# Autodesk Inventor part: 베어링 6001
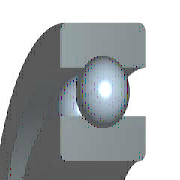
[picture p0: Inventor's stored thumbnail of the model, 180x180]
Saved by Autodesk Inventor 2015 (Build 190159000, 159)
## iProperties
IsCustomPart: 0
Created: 2015-10
Part Number: 베어링 6001
Material: Steel, Mild
Description: 깊은 그루브 볼 베어링
Document SubType Name: Modeling
Standard: KS B 2023
Designer: mdu
Standards Organization: KS
Language: ko-KR
Size Designation: 6001 - 12 x 28 x 8
Categories: <MemberInstance><Categories><Category DisplayName="샤프트 부품" InternalName="7f7aeb1f-a693-4053-b835-cee3144e0d98" Mnemonic="SHFT"><Category DisplayName="베어링" Inter
Density: 1 g/cm^3
Appearance: Steel
Author: mdu
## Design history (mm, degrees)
revolve "본체" stored, may be unused: angle "d6" = 90 deg
revolve "볼" stored, may be unused: angle "d7" = 90 deg
pattern_circular "IDS_ARRAYBALL[SIMPL:T]" dims angle "d3" = 360 deg
body "Solid1"
sketch "스케치" dims "d0" = 4.16 (= -0.26 x WD + 0.26 x BD)
  geometry: L1 (1.92, 10)-(6.08, 10); L2 (4, 10)-(4, 7.92); L3 (4, 10)-(4, 12.08); L4 (2.454, 8.608)-(0, 8.608); L5 (0, 6)-(8, 6); L6 (2.454, 11.392)-(0, 11.392); L7 (0, 14)-(8, 14); L8 (8, 6)-(8, 8.608); L9 (5.546, 8.608)-(8, 8.608); L10 (5.546, 11.392)-(8, 11.392); L11 (8, 14)-(8, 11.392); L12 (-1.4, 0)-(8.4, 0) reference; L13 (0, -0.3)-(0, 5.3) reference
  constraints: 22 end point, 4 point on line, 2 collinear, 2 perpendicular, 2 symmetric about line, 1 midpoint, 1 parallel, 14 other
  dimensions: "d9" = 12 diameter of L5 L12 (= WD); "d11" = 28 diameter of L7 L12 (= BD); "d12" = 8 distance between parallel lines of L8 L13 (= KB); "d13" = 17.216 diameter of L9 L12 (= 0.326 x BD + 0.674 x WD)
fillet "모깎기1" dims "d1" = 0.3 (= KRS)
other parameters: "WD" = 12 [user parameter; used in 5 equation terms], "BD" = 28 [user parameter; used in 5 equation terms], "KB" = 8 [user parameter; used in 1 equation term], "KRS" = 0.3 [user parameter; used in 1 equation term], "d4" = 0, "d5" = 0, "d8" = 0, "d14" = 0, "d15" = 0, "BBA" = 0 [user parameter], "BC0" = 2360000 [user parameter], "BC" = 5070000 [user parameter], "BR" = 14 (= 0.5 x BD) [user parameter], "WR" = 6 (= 0.5 x WD) [user parameter]
